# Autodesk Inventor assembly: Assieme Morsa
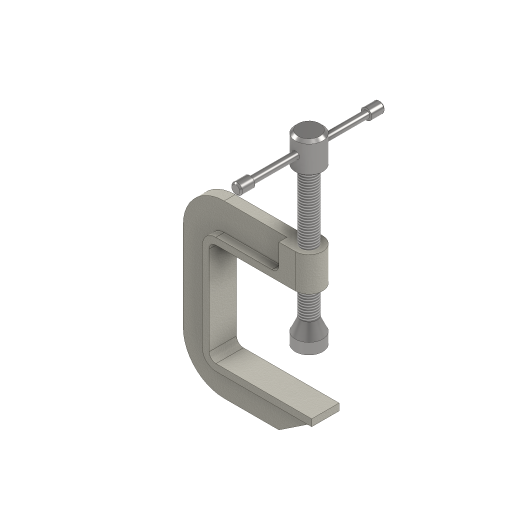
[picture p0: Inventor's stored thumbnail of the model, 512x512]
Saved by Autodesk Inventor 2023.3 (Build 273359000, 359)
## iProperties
Created: 2023-05
Part Number: Assieme Morsa
Document SubType Name: Assembly
Designer: x300
Author: x300
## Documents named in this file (7)
- C:\Users\x300\Desktop\inventor\morsa_semplice\Assieme Morsa.iam
- C:\Users\x300\Desktop\inventor\morsa_semplice\morsa.ipt
- C:\Users\x300\Desktop\inventor\morsa_semplice\mandrino.ipt
- C:\Users\x300\Desktop\inventor\morsa_semplice\maniglia.ipt
- C:\Users\x300\Desktop\inventor\morsa_semplice\tappo mandrino.ipt
- C:\Users\x300\Desktop\inventor\morsa_semplice\tappo maniglia.ipt
- C:\Users\x300\OneDrive - IIS Castelli\Documenti\Inventor\Content Center Files\R2023\it-IT\AS 1112 (2)\AS 1112 - M6  Tipo 5.ipt
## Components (7 placed, 6 different names)
1. mandrino:1 — Coincidente:1, Coincidente:2, Coincidente:3, Coincidente:4, ruota_maniglia:1, trasla_maniglia:5, Allineato:1
2. maniglia:1 — Rigido:1, Rigido:2, Coincidente:4, Allineato:1
3. tappo mandrino:1 — Coincidente:1, Coincidente:2, Rotazionale:1
4. tappo maniglia:1 — Rigido:1
5. tappo maniglia:2 — Rigido:2
6. AS 1112 (2) - Metrico M6  Tipo 5:1 — Rotazionale:1
7. morsa:1 — Coincidente:3, ruota_maniglia:1, trasla_maniglia:5
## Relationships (10: Mate 5, WeldJoint 2, RevoluteJoint 1, Angle 1, Flush 1)
- Coincidente:1 [Mate]: mandrino:1 ↔ tappo mandrino:1
- Coincidente:2 [Mate]: mandrino:1 ↔ tappo mandrino:1
- Rotazionale:1 [RevoluteJoint]: tappo mandrino:1 ↔ AS 1112 (2) - Metrico M6  Tipo 5:1
- Coincidente:3 [Mate]: mandrino:1 ↔ morsa:1
- Rigido:1 [WeldJoint]: maniglia:1 ↔ tappo maniglia:1
- Rigido:2 [WeldJoint]: maniglia:1 ↔ tappo maniglia:2
- Coincidente:4 [Mate]: mandrino:1 ↔ maniglia:1
- ruota_maniglia:1 [Angle]: mandrino:1 ↔ morsa:1
- trasla_maniglia:5 [Mate]: mandrino:1 ↔ morsa:1
- Allineato:1 [Flush]: mandrino:1 ↔ maniglia:1
